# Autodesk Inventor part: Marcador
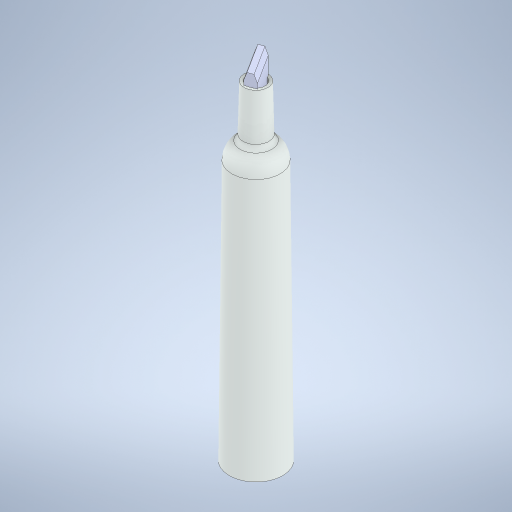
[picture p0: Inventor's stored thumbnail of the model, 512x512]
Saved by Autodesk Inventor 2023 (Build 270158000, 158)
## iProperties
Created: 2026-02
Part Number: Marcador
Material: Genérico
Document SubType Name: Modeling
Designer: JULIAN
Density: 1 g/cm^3
Appearance: Valor por defecto
Author: JULIAN
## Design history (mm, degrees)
derived "EM-COMPLETED MARKER.iam"
node "Sólido2"
node "EM-TIP.ipt:1"
node "EM-HOUSING.ipt:1"
node "EM-END CAP.ipt:1"
node "EM-INK.ipt:1"
